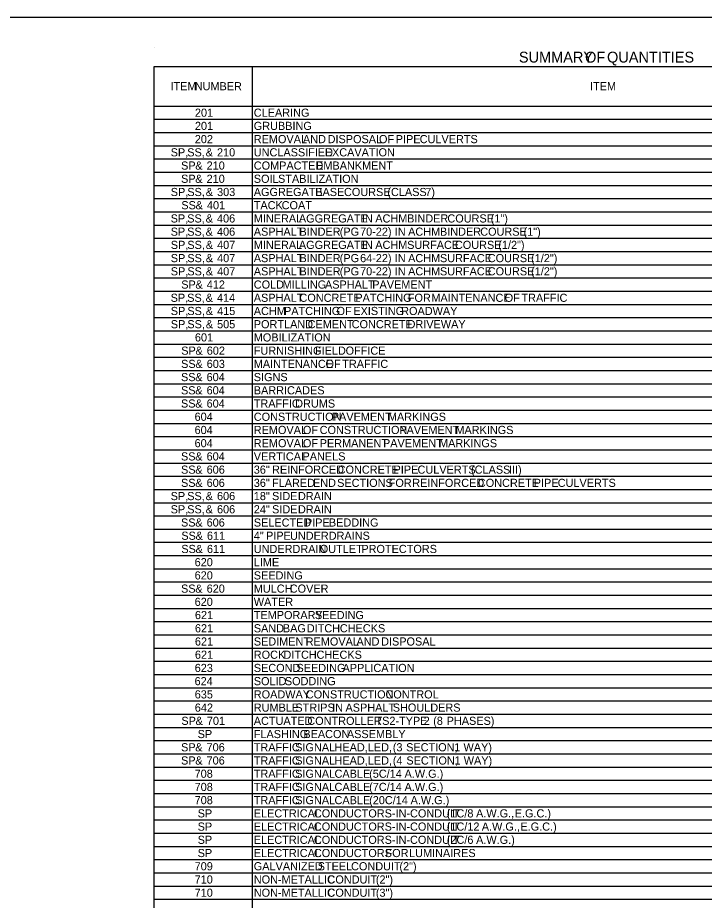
# Model space of a CAD drawing. Extents: x 3289 to 10164, y -1238 to -188.
# Drawn here: x 8800 to 9306, y -839 to -188 of the extents above; entities that cross this region are included whole.
import ezdxf

# ---------------------------------------------------------------- set-up
doc = ezdxf.new("R2010")
doc.units = 0
for name, color, linetype in [('Default', 7, 'Continuous'), ('DSN_DRFT_Named-Boundary', 7, 'Continuous'), ('DSN_QNTY_Annotation', 7, 'Continuous')]:
    doc.layers.add(name, color=color, linetype=linetype)

msp = doc.modelspace()

# ---------------------------------------------------------------- linework, layer by layer
at = {"layer": 'DSN_DRFT_Named-Boundary'}
msp.add_line((8900.84, -210.03), (8900.84, -210.03), dxfattribs=at)
msp.add_lwpolyline([(8538.57, -1237.74), (10163.57, -1237.74), (10163.57, -187.74), (8538.57, -187.74)], close=True, dxfattribs=at)
at = {"layer": 'DSN_QNTY_Annotation'}
for p, q in [((8900.84, -223.68), (8973.38, -223.68)), ((8900.84, -223.68), (9588.8, -223.68)), ((8900.84, -1023.18), (8900.84, -223.68)), ((8973.38, -1023.18), (8973.38, -223.68)), ((8900.84, -252.93), (9588.8, -252.93)), ((8973.38, -1023.18), (8973.38, -252.93)), ((8900.84, -262.68), (9588.8, -262.68)), ((8900.84, -272.43), (9588.8, -272.43)), ((8900.84, -282.18), (9588.8, -282.18)), ((8900.84, -291.93), (9588.8, -291.93)), ((8900.84, -301.68), (9588.8, -301.68)), ((8900.84, -311.43), (9588.8, -311.43)), ((8900.84, -321.18), (9588.8, -321.18)), ((8900.84, -330.93), (9588.8, -330.93)), ((8900.84, -340.68), (9588.8, -340.68)), ((8900.84, -350.43), (9588.8, -350.43)), ((8900.84, -360.18), (9588.8, -360.18)), ((8900.84, -369.93), (9588.8, -369.93)), ((8900.84, -379.68), (9588.8, -379.68)), ((8900.84, -389.43), (9588.8, -389.43)), ((8900.84, -399.18), (9588.8, -399.18)), ((8900.84, -408.93), (9588.8, -408.93)), ((8900.84, -418.68), (9588.8, -418.68)), ((8900.84, -428.43), (9588.8, -428.43)), ((8900.84, -438.18), (9588.8, -438.18)), ((8900.84, -447.93), (9588.8, -447.93)), ((8900.84, -457.68), (9588.8, -457.68)), ((8900.84, -467.43), (9588.8, -467.43)), ((8900.84, -477.18), (9588.8, -477.18)), ((8900.84, -486.93), (9588.8, -486.93)), ((8900.84, -496.68), (9588.8, -496.68)), ((8900.84, -506.43), (9588.8, -506.43)), ((8900.84, -516.18), (9588.8, -516.18)), ((8900.84, -525.93), (9588.8, -525.93)), ((8900.84, -535.68), (9588.8, -535.68)), ((8900.84, -545.43), (9588.8, -545.43)), ((8900.84, -555.18), (9588.8, -555.18)), ((8900.84, -564.93), (9588.8, -564.93)), ((8900.84, -574.68), (9588.8, -574.68)), ((8900.84, -584.43), (9588.8, -584.43)), ((8900.84, -594.18), (9588.8, -594.18)), ((8900.84, -603.93), (9588.8, -603.93)), ((8900.84, -613.68), (9588.8, -613.68)), ((8900.84, -623.43), (9588.8, -623.43)), ((8900.84, -633.18), (9588.8, -633.18)), ((8900.84, -642.93), (9588.8, -642.93)), ((8900.84, -652.68), (9588.8, -652.68)), ((8900.84, -662.43), (9588.8, -662.43)), ((8900.84, -672.18), (9588.8, -672.18)), ((8900.84, -681.93), (9588.8, -681.93)), ((8900.84, -691.68), (9588.8, -691.68)), ((8900.84, -701.43), (9588.8, -701.43)), ((8900.84, -711.18), (9588.8, -711.18)), ((8900.84, -720.93), (9588.8, -720.93)), ((8900.84, -730.68), (9588.8, -730.68)), ((8900.84, -740.43), (9588.8, -740.43)), ((8900.84, -750.18), (9588.8, -750.18)), ((8900.84, -759.93), (9588.8, -759.93)), ((8900.84, -769.68), (9588.8, -769.68)), ((8900.84, -779.43), (9588.8, -779.43)), ((8900.84, -789.18), (9588.8, -789.18)), ((8900.84, -798.93), (9588.8, -798.93)), ((8900.84, -808.68), (9588.8, -808.68)), ((8900.84, -818.43), (9588.8, -818.43)), ((8900.84, -828.18), (9588.8, -828.18)), ((8900.84, -837.93), (9588.8, -837.93))]:
    msp.add_line(p, q, dxfattribs=at)

# ---------------------------------------------------------------- texts
at = {"layer": 'Default'}
for s, height, p in [('SUMMARY', 8, (9169.76, -220.86)), (' OF', 8, (9215.57, -220.86)), (' QUANTITIES', 8, (9231.76, -220.86)), ('ITEM', 6, (8912.99, -241.31)), (' NUMBER', 6, (8928.61, -241.31)), ('ITEM', 6, (9222.19, -241.31)), ('201', 6, (8930.97, -260.81)), ('CLEARING', 6, (8974.36, -260.81)), ('201', 6, (8930.97, -270.56)), ('GRUBBING', 6, (8974.36, -270.56)), ('202', 6, (8930.89, -280.31)), ('REMOVAL', 6, (8974.36, -280.31)), (' AND', 6, (9008.36, -280.31)), (' DISPOSAL', 6, (9026.56, -280.31)), (' OF', 6, (9064.42, -280.31)), (' PIPE', 6, (9076.75, -280.31)), (' CULVERTS', 6, (9094.43, -280.31)), ('SP,', 6, (8913.1, -290.06)), (' SS,', 6, (8923.09, -290.06)), (' &', 6, (8936.69, -290.06)), (' 210', 6, (8945.03, -290.06)), ('UNCLASSIFIED', 6, (8974.36, -290.06)), (' EXCAVATION', 6, (9024.42, -290.06)), ('SP', 6, (8920.78, -299.81)), (' &', 6, (8929.01, -299.81)), (' 210', 6, (8937.36, -299.81)), ('COMPACTED', 6, (8974.36, -299.81)), (' EMBANKMENT', 6, (9018.07, -299.81)), ('SP', 6, (8920.78, -309.56)), (' &', 6, (8929.01, -309.56)), (' 210', 6, (8937.36, -309.56)), ('SOIL', 6, (8974.36, -309.56)), (' STABILIZATION', 6, (8990.03, -309.56)), ('SP,', 6, (8913.15, -319.31)), (' SS,', 6, (8923.13, -319.31)), (' &', 6, (8936.74, -319.31)), (' 303', 6, (8945.08, -319.31)), ('AGGREGATE', 6, (8974.36, -319.31)), (' BASE', 6, (9017.44, -319.31)), (' COURSE', 6, (9038.63, -319.31)), (' (CLASS', 6, (9070.59, -319.31)), (' 7)', 6, (9098.55, -319.31)), ('SS', 6, (8920.95, -329.06)), (' &', 6, (8929.26, -329.06)), (' 401', 6, (8937.6, -329.06)), ('TACK', 6, (8974.36, -329.06)), (' COAT', 6, (8992.7, -329.06)), ('SP,', 6, (8913.09, -338.81)), (' SS,', 6, (8923.07, -338.81)), (' &', 6, (8936.68, -338.81)), (' 406', 6, (8945.02, -338.81)), ('MINERAL', 6, (8974.36, -338.81)), (' AGGREGATE', 6, (9005.38, -338.81)), (' IN', 6, (9051.86, -338.81)), (' ACHM', 6, (9061.69, -338.81)), (' BINDER', 6, (9085.16, -338.81)), (' COURSE', 6, (9114.84, -338.81)), (' (1")', 6, (9146.79, -338.81)), ('SP,', 6, (8913.09, -348.56)), (' SS,', 6, (8923.07, -348.56)), (' &', 6, (8936.68, -348.56)), (' 406', 6, (8945.02, -348.56)), ('ASPHALT', 6, (8974.36, -348.56)), (' BINDER', 6, (9005.8, -348.56)), (' (PG', 6, (9035.48, -348.56)), (' 70-22)', 6, (9050.48, -348.56)), (' IN', 6, (9076.06, -348.56)), (' ACHM', 6, (9085.88, -348.56)), (' BINDER', 6, (9109.35, -348.56)), (' COURSE', 6, (9139.03, -348.56)), (' (1")', 6, (9170.98, -348.56)), ('SP,', 6, (8913.17, -358.31)), (' SS,', 6, (8923.15, -358.31)), (' &', 6, (8936.76, -358.31)), (' 407', 6, (8945.1, -358.31)), ('MINERAL', 6, (8974.36, -358.31)), (' AGGREGATE', 6, (9005.38, -358.31)), (' IN', 6, (9051.86, -358.31)), (' ACHM', 6, (9061.69, -358.31)), (' SURFACE', 6, (9085.16, -358.31)), (' COURSE', 6, (9120.4, -358.31)), (' (1/2")', 6, (9152.36, -358.31)), ('SP,', 6, (8913.17, -368.06)), (' SS,', 6, (8923.15, -368.06)), (' &', 6, (8936.76, -368.06)), (' 407', 6, (8945.1, -368.06)), ('ASPHALT', 6, (8974.36, -368.06)), (' BINDER', 6, (9005.8, -368.06)), (' (PG', 6, (9035.48, -368.06)), (' 64-22)', 6, (9050.48, -368.06)), (' IN', 6, (9076.06, -368.06)), (' ACHM', 6, (9085.88, -368.06)), (' SURFACE', 6, (9109.35, -368.06)), (' COURSE', 6, (9144.6, -368.06)), (' (1/2")', 6, (9176.55, -368.06)), ('SP,', 6, (8913.17, -377.81)), (' SS,', 6, (8923.15, -377.81)), (' &', 6, (8936.76, -377.81)), (' 407', 6, (8945.1, -377.81)), ('ASPHALT', 6, (8974.36, -377.81)), (' BINDER', 6, (9005.8, -377.81)), (' (PG', 6, (9035.48, -377.81)), (' 70-22)', 6, (9050.48, -377.81)), (' IN', 6, (9076.06, -377.81)), (' ACHM', 6, (9085.88, -377.81)), (' SURFACE', 6, (9109.35, -377.81)), (' COURSE', 6, (9144.6, -377.81)), (' (1/2")', 6, (9176.55, -377.81)), ('SP', 6, (8920.9, -387.56)), (' &', 6, (8929.13, -387.56)), (' 412', 6, (8937.47, -387.56)), ('COLD', 6, (8974.36, -387.56)), (' MILLING', 6, (8993.41, -387.56)), (' ASPHALT', 6, (9024.62, -387.56)), (' PAVEMENT', 6, (9059.46, -387.56)), ('SP,', 6, (8913.07, -397.31)), (' SS,', 6, (8923.05, -397.31)), (' &', 6, (8936.66, -397.31)), (' 414', 6, (8945, -397.31)), ('ASPHALT', 6, (8974.36, -397.31)), (' CONCRETE', 6, (9005.8, -397.31)), (' PATCHING', 6, (9046.98, -397.31)), (' FOR', 6, (9085.7, -397.31)), (' MAINTENANCE', 6, (9103.04, -397.31)), (' OF', 6, (9157.07, -397.31)), (' TRAFFIC', 6, (9169.41, -397.31)), ('SP,', 6, (8913.17, -407.06)), (' SS,', 6, (8923.16, -407.06)), (' &', 6, (8936.77, -407.06)), (' 415', 6, (8945.11, -407.06)), ('ACHM', 6, (8974.36, -407.06)), (' PATCHING', 6, (8994.42, -407.06)), (' OF', 6, (9033.14, -407.06)), (' EXISTING', 6, (9045.48, -407.06)), (' ROADWAY', 6, (9080.77, -407.06)), ('SP,', 6, (8913.17, -416.81)), (' SS,', 6, (8923.16, -416.81)), (' &', 6, (8936.77, -416.81)), (' 505', 6, (8945.11, -416.81)), ('PORTLAND', 6, (8974.36, -416.81)), (' CEMENT', 6, (9011.85, -416.81)), (' CONCRETE', 6, (9044.31, -416.81)), (' DRIVEWAY', 6, (9085.48, -416.81)), ('601', 6, (8930.97, -426.56)), ('MOBILIZATION', 6, (8974.36, -426.56)), ('SP', 6, (8920.9, -436.31)), (' &', 6, (8929.13, -436.31)), (' 602', 6, (8937.47, -436.31)), ('FURNISHING', 6, (8974.36, -436.31)), (' FIELD', 6, (9017.24, -436.31)), (' OFFICE', 6, (9039.81, -436.31)), ('SS', 6, (8920.79, -446.06)), (' &', 6, (8929.1, -446.06)), (' 603', 6, (8937.44, -446.06)), ('MAINTENANCE', 6, (8974.36, -446.06)), (' OF', 6, (9024.99, -446.06)), (' TRAFFIC', 6, (9037.33, -446.06)), ('SS', 6, (8920.71, -455.81)), (' &', 6, (8929.01, -455.81)), (' 604', 6, (8937.36, -455.81)), ('SIGNS', 6, (8974.36, -455.81)), ('SS', 6, (8920.71, -465.56)), (' &', 6, (8929.01, -465.56)), (' 604', 6, (8937.36, -465.56)), ('BARRICADES', 6, (8974.36, -465.56)), ('SS', 6, (8920.71, -475.31)), (' &', 6, (8929.01, -475.31)), (' 604', 6, (8937.36, -475.31)), ('TRAFFIC', 6, (8974.36, -475.31)), (' DRUMS', 6, (9002.66, -475.31)), ('604', 6, (8930.73, -485.06)), ('CONSTRUCTION', 6, (8974.36, -485.06)), (' PAVEMENT', 6, (9029.65, -485.06)), (' MARKINGS', 6, (9070.99, -485.06)), ('604', 6, (8930.73, -494.81)), ('REMOVAL', 6, (8974.36, -494.81)), (' OF', 6, (9008.36, -494.81)), (' CONSTRUCTION', 6, (9020.7, -494.81)), (' PAVEMENT', 6, (9079.4, -494.81)), (' MARKINGS', 6, (9120.74, -494.81)), ('604', 6, (8930.73, -504.56)), ('REMOVAL', 6, (8974.36, -504.56)), (' OF', 6, (9008.36, -504.56)), (' PERMANENT', 6, (9020.7, -504.56)), (' PAVEMENT', 6, (9067.34, -504.56)), (' MARKINGS', 6, (9108.67, -504.56)), ('SS', 6, (8920.71, -514.31)), (' &', 6, (8929.01, -514.31)), (' 604', 6, (8937.36, -514.31)), ('VERTICAL', 6, (8974.36, -514.31)), (' PANELS', 6, (9008.04, -514.31)), ('SS', 6, (8920.73, -524.06)), (' &', 6, (8929.04, -524.06)), (' 606', 6, (8937.38, -524.06)), ('36"', 6, (8974.36, -524.06)), (' REINFORCED', 6, (8985.61, -524.06)), (' CONCRETE', 6, (9033.98, -524.06)), (' PIPE', 6, (9075.16, -524.06)), (' CULVERTS', 6, (9092.84, -524.06)), (' (CLASS', 6, (9132.27, -524.06)), (' III)', 6, (9160.24, -524.06)), ('SS', 6, (8920.73, -533.81)), (' &', 6, (8929.04, -533.81)), (' 606', 6, (8937.38, -533.81)), ('36"', 6, (8974.36, -533.81)), (' FLARED', 6, (8985.61, -533.81)), (' END', 6, (9015.74, -533.81)), (' SECTIONS', 6, (9033.56, -533.81)), (' FOR', 6, (9071.59, -533.81)), (' REINFORCED', 6, (9088.93, -533.81)), (' CONCRETE', 6, (9137.31, -533.81)), (' PIPE', 6, (9178.48, -533.81)), (' CULVERTS', 6, (9196.16, -533.81)), ('SP,', 6, (8913.09, -543.56)), (' SS,', 6, (8923.07, -543.56)), (' &', 6, (8936.68, -543.56)), (' 606', 6, (8945.02, -543.56)), ('18"', 6, (8974.36, -543.56)), (' SIDE', 6, (8985.61, -543.56)), (' DRAIN', 6, (9004.67, -543.56)), ('SP,', 6, (8913.09, -553.31)), (' SS,', 6, (8923.07, -553.31)), (' &', 6, (8936.68, -553.31)), (' 606', 6, (8945.02, -553.31)), ('24"', 6, (8974.36, -553.31)), (' SIDE', 6, (8985.61, -553.31)), (' DRAIN', 6, (9004.67, -553.31)), ('SS', 6, (8920.73, -563.06)), (' &', 6, (8929.04, -563.06)), (' 606', 6, (8937.38, -563.06)), ('SELECTED', 6, (8974.36, -563.06)), (' PIPE', 6, (9009.83, -563.06)), (' BEDDING', 6, (9027.51, -563.06)), ('SS', 6, (8920.95, -572.81)), (' &', 6, (8929.26, -572.81)), (' 611', 6, (8937.6, -572.81)), ('4"', 6, (8974.36, -572.81)), (' PIPE', 6, (8981.17, -572.81)), (' UNDERDRAINS', 6, (8998.84, -572.81)), ('SS', 6, (8920.95, -582.56)), (' &', 6, (8929.26, -582.56)), (' 611', 6, (8937.6, -582.56)), ('UNDERDRAIN', 6, (8974.36, -582.56)), (' OUTLET', 6, (9020.74, -582.56)), (' PROTECTORS', 6, (9051.42, -582.56)), ('620', 6, (8930.77, -592.31)), ('LIME', 6, (8974.36, -592.31)), ('620', 6, (8930.77, -602.06)), ('SEEDING', 6, (8974.36, -602.06)), ('SS', 6, (8920.74, -611.81)), (' &', 6, (8929.05, -611.81)), (' 620', 6, (8937.39, -611.81)), ('MULCH', 6, (8974.36, -611.81)), (' COVER', 6, (8998.64, -611.81)), ('620', 6, (8930.77, -621.56)), ('WATER', 6, (8974.36, -621.56)), ('621', 6, (8930.97, -631.31)), ('TEMPORARY', 6, (8974.36, -631.31)), (' SEEDING', 6, (9017.19, -631.31)), ('621', 6, (8930.97, -641.06)), ('SAND', 6, (8974.36, -641.06)), (' BAG', 6, (8993.58, -641.06)), (' DITCH', 6, (9011.21, -641.06)), (' CHECKS', 6, (9035.57, -641.06)), ('621', 6, (8930.97, -650.81)), ('SEDIMENT', 6, (8974.36, -650.81)), (' REMOVAL', 6, (9010.4, -650.81)), (' AND', 6, (9047.81, -650.81)), (' DISPOSAL', 6, (9066, -650.81)), ('621', 6, (8930.97, -660.56)), ('ROCK', 6, (8974.36, -660.56)), (' DITCH', 6, (8994.01, -660.56)), (' CHECKS', 6, (9018.37, -660.56)), ('623', 6, (8930.82, -670.31)), ('SECOND', 6, (8974.36, -670.31)), (' SEEDING', 6, (9003.58, -670.31)), (' APPLICATION', 6, (9037.56, -670.31)), ('624', 6, (8930.73, -680.06)), ('SOLID', 6, (8974.36, -680.06)), (' SODDING', 6, (8995.03, -680.06)), ('635', 6, (8930.84, -689.81)), ('ROADWAY', 6, (8974.36, -689.81)), (' CONSTRUCTION', 6, (9010.48, -689.81)), (' CONTROL', 6, (9069.18, -689.81)), ('642', 6, (8930.89, -699.56)), ('RUMBLE', 6, (8974.36, -699.56)), (' STRIPS', 6, (9002.81, -699.56)), (' IN', 6, (9029.9, -699.56)), (' ASPHALT', 6, (9039.72, -699.56)), (' SHOULDERS', 6, (9074.57, -699.56)), (' (8', 6, (9104.38, -709.31)), (' PHASES)', 6, (9114.29, -709.31)), ('SP', 6, (8920.99, -709.31)), (' &', 6, (8929.22, -709.31)), (' 701', 6, (8937.56, -709.31)), ('ACTUATED', 6, (8974.36, -709.31)), (' CONTROLLER', 6, (9011.61, -709.31)), (' TS2-TYPE', 6, (9061.82, -709.31)), (' 2', 6, (9097.4, -709.31)), ('SP', 6, (8932.99, -719.06)), ('FLASHING', 6, (8974.36, -719.06)), (' BEACON', 6, (9008.67, -719.06)), (' ASSEMBLY', 6, (9040.77, -719.06)), (' (3', 6, (9074.6, -728.81)), (' WAY)', 6, (9126.72, -728.81)), ('SP', 6, (8920.77, -728.81)), (' &', 6, (8929, -728.81)), (' 706', 6, (8937.34, -728.81)), ('TRAFFIC', 6, (8974.36, -728.81)), (' SIGNAL', 6, (9002.66, -728.81)), (' HEAD,', 6, (9031.64, -728.81)), (' LED,', 6, (9056.19, -728.81)), (' SECTION,', 6, (9084.43, -728.81)), (' 1', 6, (9119.93, -728.81)), ('SP', 6, (8920.77, -738.56)), (' &', 6, (8929, -738.56)), (' 706', 6, (8937.34, -738.56)), ('TRAFFIC', 6, (8974.36, -738.56)), (' SIGNAL', 6, (9002.66, -738.56)), (' HEAD,', 6, (9031.64, -738.56)), (' LED,', 6, (9056.19, -738.56)), (' (4', 6, (9074.6, -738.56)), (' SECTION,', 6, (9084.6, -738.56)), (' 1', 6, (9120.1, -738.56)), (' WAY)', 6, (9126.89, -738.56)), (' (5C/14', 6, (9057.16, -748.31)), (' A.W.G.)', 6, (9083.27, -748.31)), ('708', 6, (8930.77, -748.31)), ('TRAFFIC', 6, (8974.36, -748.31)), (' SIGNAL', 6, (9002.66, -748.31)), (' CABLE', 6, (9031.64, -748.31)), ('708', 6, (8930.77, -758.06)), ('TRAFFIC', 6, (8974.36, -758.06)), (' SIGNAL', 6, (9002.66, -758.06)), (' CABLE', 6, (9031.64, -758.06)), (' (7C/14', 6, (9057.16, -758.06)), (' A.W.G.)', 6, (9083.27, -758.06)), (' (20C/14', 6, (9057.16, -767.81)), (' A.W.G.)', 6, (9087.71, -767.81)), ('708', 6, (8930.77, -767.81)), ('TRAFFIC', 6, (8974.36, -767.81)), (' SIGNAL', 6, (9002.66, -767.81)), (' CABLE', 6, (9031.64, -767.81)), ('SP', 6, (8932.99, -777.56)), ('ELECTRICAL', 6, (8974.36, -777.56)), (' CONDUCTORS-IN-CONDUIT', 6, (9016.44, -777.56)), (' (1C/8', 6, (9114.39, -777.56)), (' A.W.G.,', 6, (9135.97, -777.56)), (' E.G.C.)', 6, (9164.45, -777.56)), (' (1C/12', 6, (9114.39, -787.31)), (' E.G.C.)', 6, (9168.67, -787.31)), ('SP', 6, (8932.99, -787.31)), ('ELECTRICAL', 6, (8974.36, -787.31)), (' CONDUCTORS-IN-CONDUIT', 6, (9016.44, -787.31)), (' A.W.G.,', 6, (9140.19, -787.31)), ('SP', 6, (8932.99, -797.06)), ('ELECTRICAL', 6, (8974.36, -797.06)), (' CONDUCTORS-IN-CONDUIT', 6, (9016.44, -797.06)), (' (2C/6', 6, (9114.39, -797.06)), (' A.W.G.)', 6, (9136.01, -797.06)), ('SP', 6, (8932.99, -806.81)), ('ELECTRICAL', 6, (8974.36, -806.81)), (' CONDUCTORS', 6, (9016.44, -806.81)), (' FOR', 6, (9069.26, -806.81)), (' LUMINAIRES', 6, (9086.6, -806.81)), ('709', 6, (8930.78, -816.56)), ('GALVANIZED', 6, (8974.36, -816.56)), (' STEEL', 6, (9019.24, -816.56)), (' CONDUIT', 6, (9043.84, -816.56)), (' (2")', 6, (9079.48, -816.56)), ('710', 6, (8930.77, -826.31)), ('NON-METALLIC', 6, (8974.36, -826.31)), (' CONDUIT', 6, (9026.45, -826.31)), (' (2")', 6, (9062.1, -826.31)), ('710', 6, (8930.77, -836.06)), ('NON-METALLIC', 6, (8974.36, -836.06)), (' CONDUIT', 6, (9026.45, -836.06)), (' (3")', 6, (9062.1, -836.06))]:
    msp.add_text(s, height=height, dxfattribs=at).set_placement(p)

doc.saveas('drawing.dxf')
